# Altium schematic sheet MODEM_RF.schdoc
size 127 x 101 mm
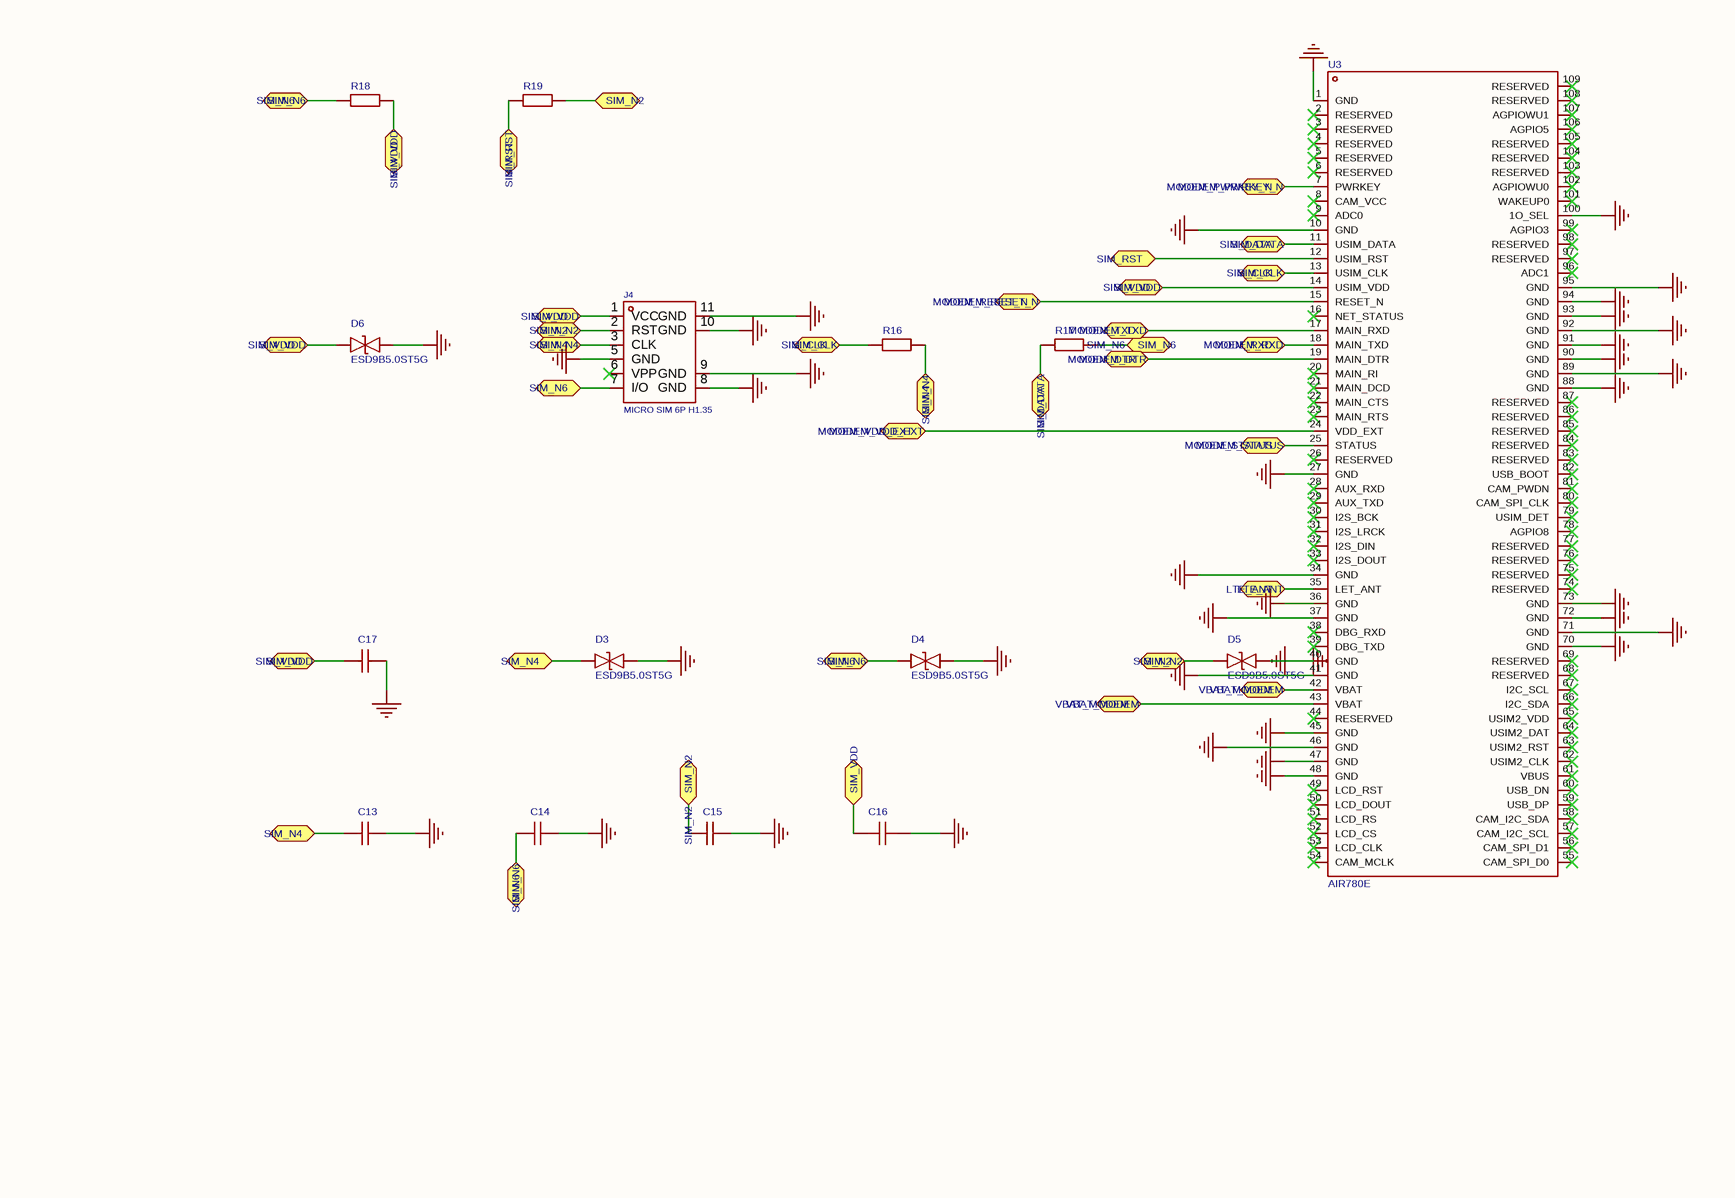
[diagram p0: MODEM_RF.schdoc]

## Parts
C13  (no value)  [C0402]
C14  (no value)  [C0402]
C15  (no value)  [C0402]
C16  (no value)  [C0402]
C17  (no value)  [C0402]
D3  ESD9B5.0ST5G  [SOD-923_L0.8-W0.6-LS1.0-BI]
D4  ESD9B5.0ST5G  [SOD-923_L0.8-W0.6-LS1.0-BI]
D5  ESD9B5.0ST5G  [SOD-923_L0.8-W0.6-LS1.0-BI]
D6  ESD9B5.0ST5G  [SOD-923_L0.8-W0.6-LS1.0-BI]
J4  MICRO SIM 6P H1.35  [SIM-SMD_MICRO-SIM-6P-H1.35-1]
R16  (no value)  [R0402]
R17  (no value)  [R0402]
R18  (no value)  [R0402]
R19  (no value)  [R0402]
U3  AIR780E  [LGA-109_L17.7-W15.8-AIR780E]

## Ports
LTE_ANT (bidir), MODEM_DTR (bidir), MODEM_PWRKEY_N (bidir), MODEM_RESET_N (bidir), MODEM_RXD (bidir), MODEM_STATUS (bidir), MODEM_TXD (bidir), MODEM_VDD_EXT (bidir), SIM_CLK (bidir), SIM_DATA (bidir), SIM_N2 (bidir), SIM_N4 (bidir), SIM_N6 (bidir), SIM_RST (bidir), SIM_VDD (bidir), VBAT_MODEM (bidir)

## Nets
GND: C13.2 C14.2 C15.2 C16.2 C17.2 D3.2 D4.2 D5.2 D6.2 J4.5(GND) J4.8(GND) J4.9(GND) J4.10(GND) J4.11(GND) U3.1(GND) U3.10(GND) U3.27(GND) U3.34(GND) U3.36(GND) U3.37(GND) U3.40(GND) U3.41(GND) U3.45(GND) U3.46(GND) U3.47(GND) U3.48(GND) U3.70(GND) U3.71(GND) U3.72(GND) U3.73(GND) U3.88(GND) U3.89(GND) U3.90(GND) U3.91(GND) U3.92(GND) U3.93(GND) U3.94(GND) U3.95(GND) U3.100(1O_SEL)
LTE_ANT: U3.35(LET_ANT) ; port LTE_ANT
MODEM_DTR: U3.19(MAIN_DTR) ; port MODEM_DTR
MODEM_PWRKEY_N: U3.7(PWRKEY) ; port MODEM_PWRKEY_N
MODEM_RESET_N: U3.15(RESET_N) ; port MODEM_RESET_N
MODEM_RXD: U3.18(MAIN_TXD) ; port MODEM_RXD
MODEM_STATUS: U3.25(STATUS) ; port MODEM_STATUS
MODEM_TXD: U3.17(MAIN_RXD) ; port MODEM_TXD
MODEM_VDD_EXT: U3.24(VDD_EXT) ; port MODEM_VDD_EXT
SIM_CLK: R16.1 U3.13(USIM_CLK) ; port SIM_CLK
SIM_DATA: R17.1 U3.11(USIM_DATA) ; port SIM_DATA
SIM_N2: C15.1 D5.1 J4.2(RST) R19.2 ; port SIM_N2
SIM_N4: C13.1 D3.1 J4.3(CLK) R16.2 ; port SIM_N4
SIM_N6: C14.1 D4.1 J4.7(I/O) R17.2 R18.1 ; port SIM_N6
SIM_RST: R19.1 U3.12(USIM_RST) ; port SIM_RST
SIM_VDD: C16.1 C17.1 D6.1 J4.1(VCC) R18.2 U3.14(USIM_VDD) ; port SIM_VDD
VBAT_MODEM: U3.42(VBAT) U3.43(VBAT) ; port VBAT_MODEM

Not connected (* = marked no-connect by the designer): J4 6(VPP)*; U3 2(RESERVED)* 3(RESERVED)* 4(RESERVED)* 5(RESERVED)* 6(RESERVED)* 8(CAM_VCC)* 9(ADC0)* 16(NET_STATUS)* 20(MAIN_RI)* 21(MAIN_DCD)* 22(MAIN_CTS)* 23(MAIN_RTS)* 26(RESERVED)* 28(AUX_RXD)* 29(AUX_TXD)* 30(I2S_BCK)* 31(I2S_LRCK)* 32(I2S_DIN)* 33(I2S_DOUT)* 38(DBG_RXD)* 39(DBG_TXD)* 44(RESERVED)* 49(LCD_RST)* 50(LCD_DOUT)* 51(LCD_RS)* 52(LCD_CS)* 53(LCD_CLK)* 54(CAM_MCLK)* 55(CAM_SPI_D0)* 56(CAM_SPI_D1)* 57(CAM_I2C_SCL)* 58(CAM_I2C_SDA)* 59(USB_DP)* 60(USB_DN)* 61(VBUS)* 62(USIM2_CLK)* 63(USIM2_RST)* 64(USIM2_DAT)* 65(USIM2_VDD)* 66(I2C_SDA)* 67(I2C_SCL)* 68(RESERVED)* 69(RESERVED)* 74(RESERVED)* 75(RESERVED)* 76(RESERVED)* 77(RESERVED)* 78(AGPIO8)* 79(USIM_DET)* 80(CAM_SPI_CLK)* 81(CAM_PWDN)* 82(USB_BOOT)* 83(RESERVED)* 84(RESERVED)* 85(RESERVED)* 86(RESERVED)* 87(RESERVED)* 96(ADC1)* 97(RESERVED)* 98(RESERVED)* 99(AGPIO3)* 101(WAKEUP0)* 102(AGPIOWU0)* 103(RESERVED)* 104(RESERVED)* 105(RESERVED)* 106(AGPIO5)* 107(AGPIOWU1)* 108(RESERVED)* 109(RESERVED)*

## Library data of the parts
C13-C15 C17 = 0402CG330J500NT: Manufacturer: FH(风华); Add into BOM: yes; ModelId: 36a51122f27c49738f86b3bfa98863e00819f05c4eef4c71ace90d822a990e87; ModelName: C0402_L1.0-W0.5-H0.5; ModelTransform: 39.37,19.685,0,0,0,0,0,0,0
C16 = CL05B104KO5NNNC: Manufacturer: SAMSUNG(三星); Add into BOM: yes; ModelId: 36a51122f27c49738f86b3bfa98863e00819f05c4eef4c71ace90d822a990e87; ModelName: C0402_L1.0-W0.5-H0.5; ModelTransform: 39.37,19.685,0,0,0,0,0,0,0
D3-D6 = ESD9B5.0ST5G_C3021104: Manufacturer: TECH PUBLIC(台舟); Add into BOM: yes; ModelId: 660ac8bf102d4748bf6f5373c8c7078e0819f05c4eef4c71ace90d822a990e87; ModelName: SOD-923_L0.8-W0.6-H0.5-LS1.0; ModelTransform: 39.37,23.622,0,0,0,0,0,0,0
J4 = MICRO SIM 6P H1.35: Manufacturer: SHOU HAN(首韩); Add into BOM: yes; ModelId: 2d1835d72d124c46bdf4a050fa5337ae0819f05c4eef4c71ace90d822a990e87; ModelTransform: 649.605,677.164,0,0,0,0,0,-20.354,0
R16 R17 R19 = 0402WGF220JTCE: Manufacturer: UNI-ROYAL(厚声); Add into BOM: yes; ModelId: 98c88bc2b9094f218f3a3e30a70127380819f05c4eef4c71ace90d822a990e87; ModelName: R0402_L1.0-W0.5-H0.4; ModelTransform: 39.37,19.685,0,0,0,0,0,0,0
R18 = 0402WGF1002TCE: Manufacturer: UNI-ROYAL(厚声); Add into BOM: yes; ModelId: 98c88bc2b9094f218f3a3e30a70127380819f05c4eef4c71ace90d822a990e87; ModelName: R0402_L1.0-W0.5-H0.4; ModelTransform: 39.37,19.685,0,0,0,0,0,0,0
U3 = AIR780E: Add into BOM: yes; ModelId: 60a91e7d274d4b149e710c2e3cbeee920819f05c4eef4c71ace90d822a990e87; ModelTransform: 622.046,696.84892,0,0,0,0,0,0.005,0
